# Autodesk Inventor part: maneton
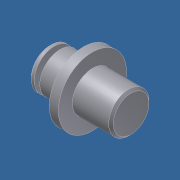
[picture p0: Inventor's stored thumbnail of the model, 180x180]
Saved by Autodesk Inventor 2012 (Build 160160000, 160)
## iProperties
Created: 2011-07
Part Number: maneton
Document SubType Name: Modeling
Designer: Laur
Density: 7.85 g/cm^3
Material: Acier allié
Mass: 0.637262 g
Surface Area: 1.50499 cm^2
Volume: 0.0811799 cm^3
Author: Laur
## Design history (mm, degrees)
sketch "Esquisse1"
  geometry: L1 (0, 0)-(7.2, 0); L2 (0, 0)-(0, 1.57); L3 (0, 1.57)-(0.2, 1.77); L4 (0.2, 1.77)-(0.44, 1.77); L5 (0.44, 1.77)-(0.44, 1); L6 (0.44, 1)-(0.94, 1); L7 (0.94, 1)-(0.94, 1.77); L8 (0.94, 1.77)-(3, 1.77); L9 (3, 1.77)-(3, 3); L10 (3, 3)-(3.8, 3); L11 (3.8, 3)-(3.8, 1.77); L12 (3.8, 1.77)-(7.2, 1.77); L13 (7.2, 1.77)-(7.2, 0)
  constraints: 27 end point, 6 parallel, 3 perpendicular, 2 collinear, 1 horizontal
  dimensions: "d0" = 0.5 distance between parallel lines of L7 L5; "d1" = 3.54 diameter of L4 L1; "d2" = 3.54 diameter of L8 L1 (= d1); "d3" = 3.54 diameter of L12 L1 (= d1); "d4" = 6 diameter of L10 L1; "d5" = 0.8 distance between parallel lines of L11 L9; "d6" = 7.2 distance between parallel lines of L13 L2; "d7" = 2 diameter of L6 L1; "d8" = 0.44 distance between parallel lines of L5 L2; "d9" = 45 deg angle of L2 L3; "d10" = 0.2 distance from line of L2 L3.end; "d11" = 3 distance between parallel lines of L9 L2
revolve "arbre dont Ø3,54" sketch "Esquisse1" stored, may be unused: angle "d12" = 90 deg
chamfer "Chanfrein 0,2 à 45°" distance "d13" = 0.2; stored, may be unused: second distance "d14" = 2, angle "d15" = 45 deg
node "Solide1"
node "Corps solides"
node "Corps surfaciques"
